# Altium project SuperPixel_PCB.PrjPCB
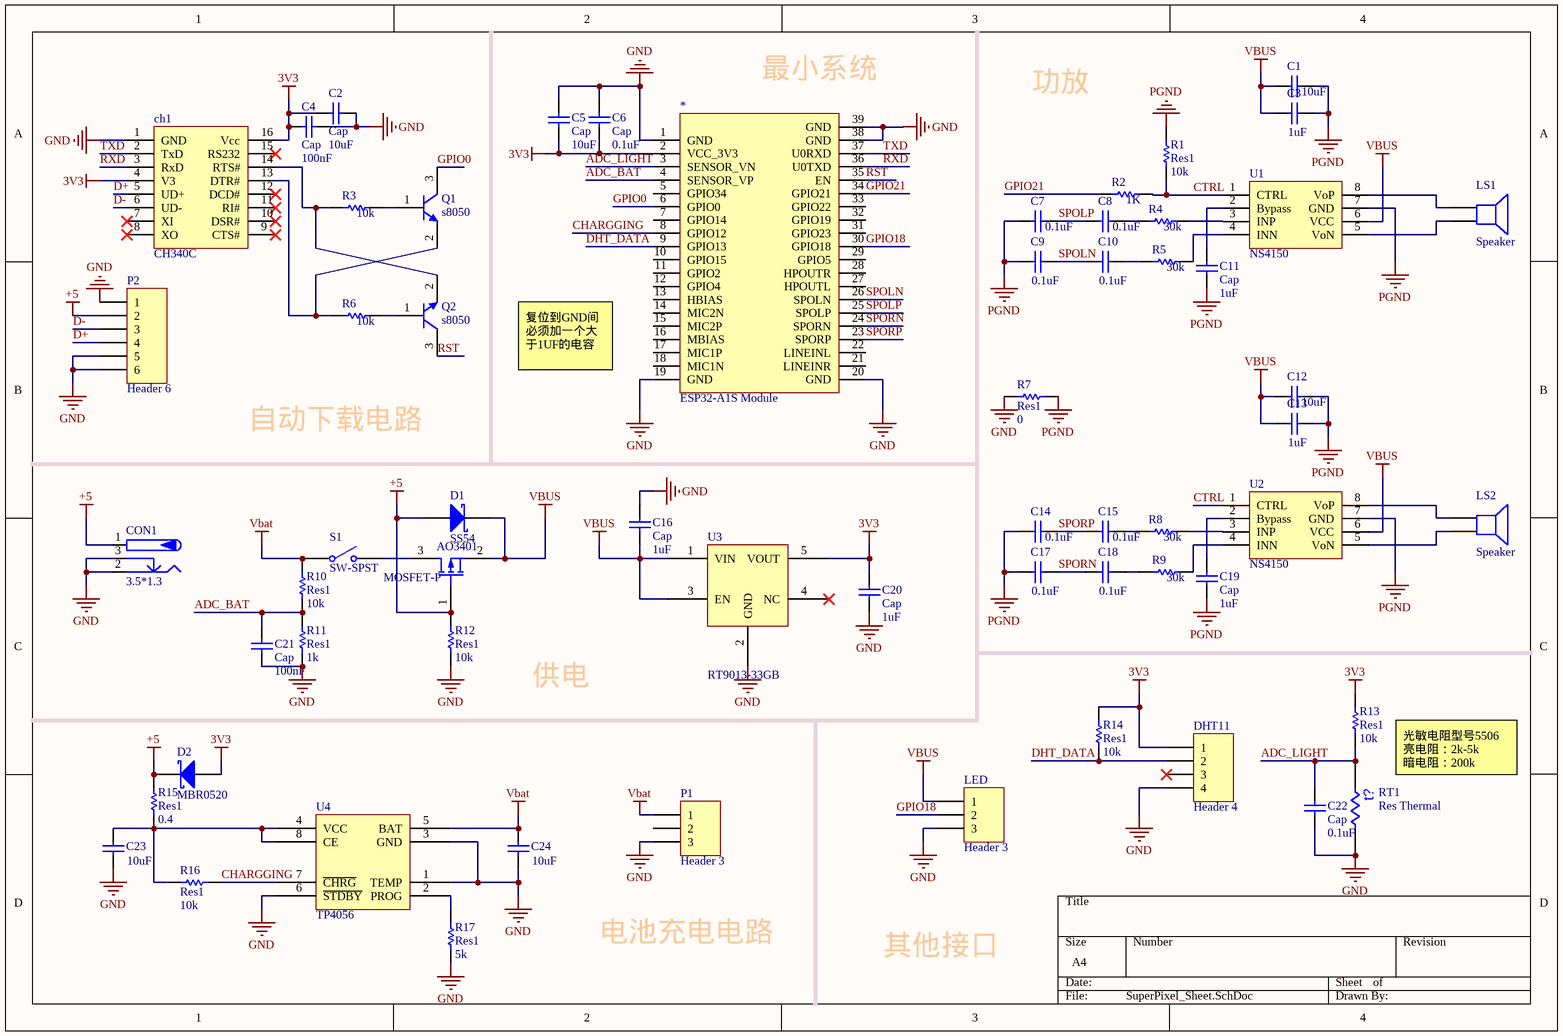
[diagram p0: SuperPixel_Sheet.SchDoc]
1 sheet, 61 parts. Net scope: global (net labels, ports and power ports of the same name join across sheets).
Board file: SuperPixel_PCB.PcbDoc

## Sheet SuperPixel_Sheet.SchDoc
size A4

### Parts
*  ESP32-A1S Module  [ESP32-A1S Module]
AO3401  MOSFET-P  [sot23]
C1  value 10uF  [1206c]  (hidden comment: Cap)
C2  Cap  value 10uF  [1206c]
C3  value 1uF  [0805-1c]  (hidden comment: Cap)
C4  Cap  value 100nF  [0603c]
C5  Cap  value 10uF  [1206c]
C6  Cap  value 0.1uF  [0603c]
C7  value 0.1uF  [0603c]  (hidden comment: Cap)
C8  value 0.1uF  [0603c]  (hidden comment: Cap)
C9  value 0.1uF  [0603c]  (hidden comment: Cap)
C10  value 0.1uF  [0603c]  (hidden comment: Cap)
C11  Cap  value 1uF  [0805-1c]
C12  value 10uF  [1206c]  (hidden comment: Cap)
C13  value 1uF  [0805-1c]  (hidden comment: Cap)
C14  value 0.1uF  [0603c]  (hidden comment: Cap)
C15  value 0.1uF  [0603c]  (hidden comment: Cap)
C16  Cap  value 1uF  [0805-1c]
C17  value 0.1uF  [0603c]  (hidden comment: Cap)
C18  value 0.1uF  [0603c]  (hidden comment: Cap)
C19  Cap  value 1uF  [0805-1c]
C20  Cap  value 1uF  [0805-1c]
C21  Cap  value 100nF  [0603c]
C22  Cap  value 0.1uF  [0603c]
C23  value 10uF  [1206c]  (hidden comment: Cap)
C24  value 10uF  [1206c]  (hidden comment: Cap)
ch1  CH340C  [SOP16_M]
CON1  3.5*1.3  [DC-005]
D1  SS54  [SMA]
D2  MBR0520  [SOD123]
DHT11  Header 4  [HDR1X4]
LED  Header 3  [HDR1X3]
LS1  Speaker  [PIN2]
LS2  Speaker  [PIN2]
P1  Header 3  [HDR1X3]
P2  Header 6  [USB-MICRO]
Q1  s8050  [sot-23]
Q2  s8050  [sot-23]
R1  Res1  value 10k  [0603r]
R2  value 1K  [0603r]  (hidden comment: Res1)
R3  value 10k  [0603r]  (hidden comment: Res1)
R4  value 30k  [0603r]  (hidden comment: Res1)
R5  value 30k  [0603r]  (hidden comment: Res1)
R6  value 10k  [0603r]  (hidden comment: Res1)
R7  Res1  value 0  [0603r]
R8  value 30k  [0603r]  (hidden comment: Res1)
R9  value 30k  [0603r]  (hidden comment: Res1)
R10  Res1  value 10k  [0603r]
R11  Res1  value 1k  [0603r]
R12  Res1  value 10k  [0603r]
R13  Res1  value 10k  [0603r]
R14  Res1  value 10k  [0603r]
R15  Res1  value 0.4  [2512-r]
R16  Res1  value 10k  [0603r]
R17  Res1  value 5k  [0603r]
RT1  Res Thermal  [HDR1X2]
S1  SW-SPST  [HDR1X2]
U1  NS4150  [SOP8]
U2  NS4150  [SOP8]
U3  RT9013-33GB  [sot23-5]
U4  TP4056  [SOP8]

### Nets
3V3: *.2(VCC_3V3) C2.2 C4.2 C5.1 C6.1 C20.2 ch1.4(V3) ch1.16(Vcc) D2.1(A) DHT11.1 R13.2 R14.2 U3.5(VOUT)
+5: AO3401.1(G) CON1.1 D1.1(A) D2.2(K) P2.2 R12.2 R15.2
GND: *.1(GND) *.19(GND) *.20(GND) *.38(GND) *.39(GND) C2.1 C4.1 C5.2 C6.2 C16.1 C20.1 C21.1 C22.1 C23.1 C24.1 ch1.1(GND) CON1.2 CON1.3 DHT11.4 LED.3 P1.3 P2.1 P2.5 P2.6 R7.1 R11.1 R12.1 R17.1 RT1.2 U3.2(GND) U4.1(TEMP) U4.3(GND) U4.6(~{STDBY})
PGND: C1.2 C3.2 C7.2 C9.2 C11.1 C12.2 C13.2 C14.2 C17.2 C19.1 R1.2 R7.2 U1.7(GND) U2.7(GND)
Vbat: C24.2 P1.1 R10.2 S1.1(COMMON) U4.5(BAT)
VBUS: AO3401.2(S) C1.1 C3.1 C12.1 C13.1 C16.2 D1.2(K) LED.1 U1.6(VCC) U2.6(VCC) U3.1(VIN) U3.3(EN)
ADC_BAT: *.4(SENSOR_VP) C21.2 R10.1 R11.2
ADC_LIGHT: *.3(SENSOR_VN) C22.2 R13.1 RT1.1
CHARGGING: *.8(GPIO12) R16.2 U4.7(~{CHRG})
CTRL: R1.1 R2.2 U1.1(CTRL) U2.1(CTRL)
D+: ch1.5(UD+) P2.4
D-: ch1.6(UD-) P2.3
DHT_DATA: *.9(GPIO13) DHT11.2 R14.1
GPIO0: *.6(GPIO0) Q1.3(C)
GPIO18: *.30(GPIO18) LED.2
GPIO21: *.34(GPIO21) R2.1
RST: *.35(EN) Q2.3(C)
RXD: *.36(U0TXD) ch1.3(RxD)
SPOLN: *.26(SPOLN) C9.1 C10.1
SPOLP: *.25(SPOLP) C7.1 C8.1
SPORN: *.24(SPORN) C17.1 C18.1
SPORP: *.23(SPORP) C14.1 C15.1
TXD: *.37(U0RXD) ch1.2(TxD)
NetAO3401_3: AO3401.3(D) S1.2(NO)
NetC8_2: C8.2 R4.1
NetC10_2: C10.2 R5.1
NetC11_2: C11.2 U1.2(Bypass)
NetC15_2: C15.2 R8.1
NetC18_2: C18.2 R9.1
NetC19_2: C19.2 U2.2(Bypass)
NetC23_2: C23.2 R15.1 R16.1 U4.4(VCC) U4.8(CE)
Netch1_13: ch1.13(DTR#) Q1.2(E) R6.1
Netch1_14: ch1.14(RTS#) Q2.2(E) R3.1
NetLS1_1: LS1.1 U1.8(VoP)
NetLS1_2: LS1.2 U1.5(VoN)
NetLS2_1: LS2.1 U2.8(VoP)
NetLS2_2: LS2.2 U2.5(VoN)
NetQ1_1: Q1.1(B) R3.2
NetQ2_1: Q2.1(B) R6.2
NetR4_2: R4.2 U1.3(INP)
NetR5_2: R5.2 U1.4(INN)
NetR8_2: R8.2 U2.3(INP)
NetR9_2: R9.2 U2.4(INN)
NetR17_2: R17.2 U4.2(PROG)

Not connected (* = marked no-connect by the designer): * 5(GPIO34) 7(GPIO14) 10(GPIO15) 11(GPIO2) 12(GPIO4) 13(HBIAS) 14(MIC2N) 15(MIC2P) 16(MBIAS) 17(MIC1P) 18(MIC1N) 21(LINEINR) 22(LINEINL) 27(HPOUTL) 28(HPOUTR) 29(GPIO5) 31(GPIO23) 32(GPIO19) 33(GPIO22); ch1 7(XI)* 8(XO)* 9(CTS#)* 10(DSR#)* 11(RI#)* 12(DCD#)* 15(RS232)*; DHT11 3*; P1 2; U3 4(NC)*

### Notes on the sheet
- (near *) 最小系统
- 功放
- 复位到GND间必须加一个大于1UF的电容
- 自动下载电路
- 供电
- 光敏电阻型号5506
  亮电阻：2k-5k
  暗电阻：200k
- 电池充电电路
- 其他接口

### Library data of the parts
AO3401 = MOSFET-P: P-Channel MOSFET
C1-C24 = Cap: Capacitor
ch1 = CH340G: 串口转USB; 版权归属: 源创客
CON1 = P-DC: 低压电源接口; BOM名称: DC电源接口; 版权归属: 源创客
D1 D2 = D Schottky: Schottky Diode
DHT11 = Header 4: Header, 4-Pin
LED P1 = Header 3: Header, 3-Pin
LS1 LS2 = Speaker: Loudspeaker
P2 = Header 6: Header, 6-Pin; pin to pad: 1>0 2>1 3>2 4>3 5>4 6>5
Q1 Q2 = NPN: NPN Bipolar Transistor
R1-R17 = Res1: Resistor
RT1 = Res Thermal: Thermistor
S1 = SW-SPST: Single-Pole, Single-Throw Switch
